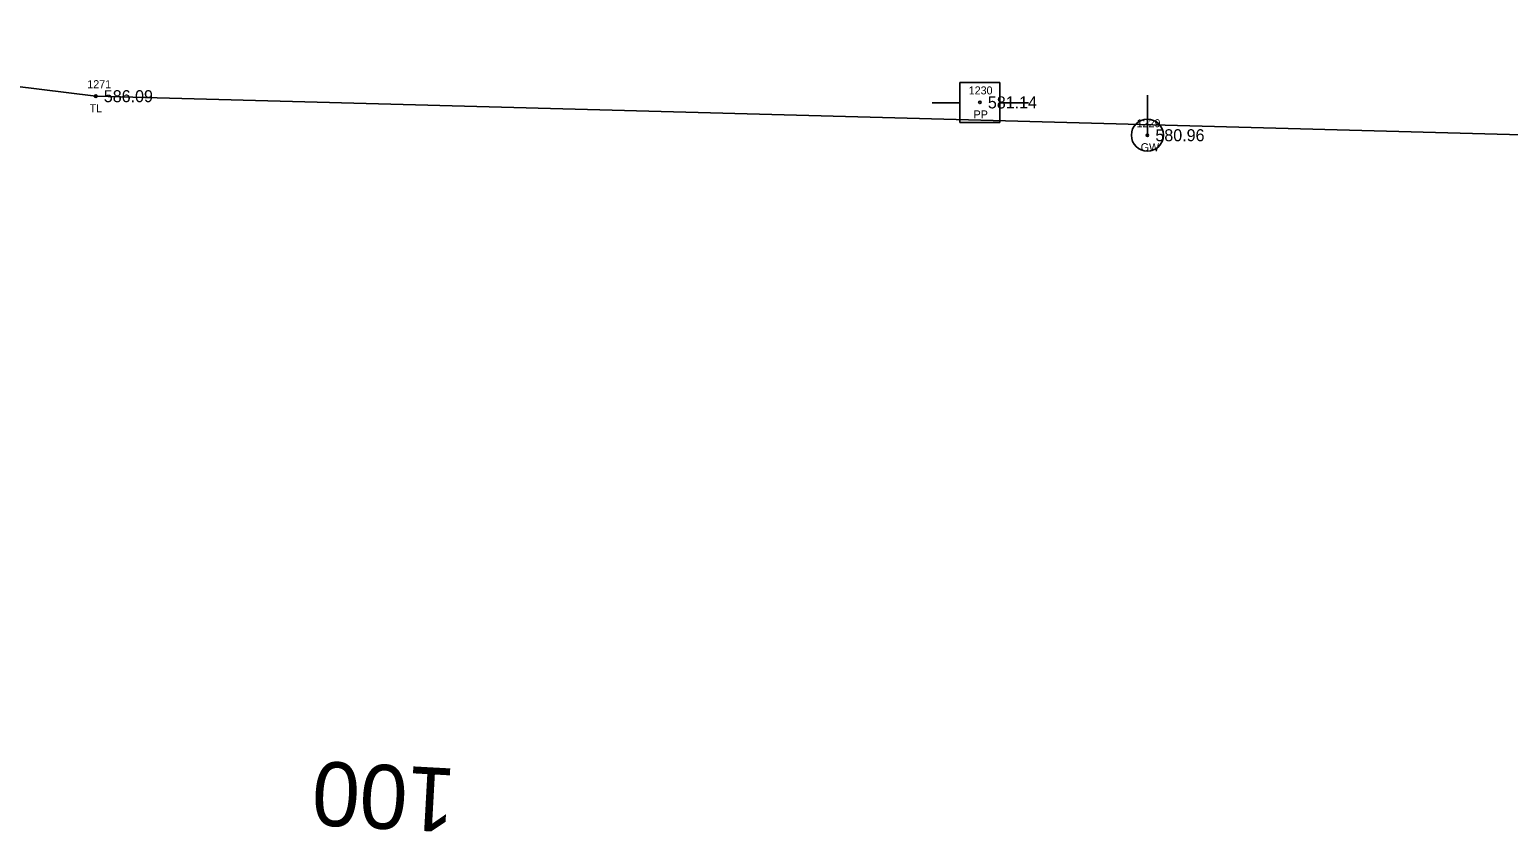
# Model space of a CAD drawing. Extents: x 1529475 to 1532053, y 876698 to 877911.
# Drawn here: x 1530599.7 to 1530784.5, y 877153.9 to 877254.2 of the extents above; entities that cross this region are included whole.
import ezdxf

# ---------------------------------------------------------------- set-up
doc = ezdxf.new("R2010")
doc.units = 0
for name, color, linetype in [('RD_EX_TX_UT_ELEV', 7, 'Continuous'), ('RD_EX_TX_VEG_ELEV', 7, 'Continuous'), ('RD_EX_UT', 7, 'Continuous'), ('RD_EX_UT_txCode', 7, 'Continuous'), ('RD_EX_VEG', 7, 'Continuous'), ('RD_EX_VEG_txCode', 7, 'Continuous'), ('RD_HC_Survey_ELEV', 7, 'Continuous'), ('RD_HC_TX_Sta50', 7, 'Continuous'), ('RD_SMD_Locator', 7, 'Continuous')]:
    doc.layers.add(name, color=color, linetype=linetype)

msp = doc.modelspace()

# ---------------------------------------------------------------- linework, layer by layer
at = {"layer": 'RD_EX_UT'}
for p, q in [((1530720.91, 877247.58), (1530715.91, 877247.58)), ((1530715.91, 877247.58), (1530715.91, 877242.58)), ((1530720.91, 877242.58), (1530720.91, 877247.58)), ((1530739.35, 877240.97), (1530739.35, 877245.97)), ((1530712.48, 877245.01), (1530715.95, 877245.01)), ((1530720.84, 877245.01), (1530724.48, 877245.01)), ((1530715.91, 877242.58), (1530720.91, 877242.58))]:
    msp.add_line(p, q, dxfattribs=at)
msp.add_circle((1530739.35, 877240.97), 2, dxfattribs=at)
at = {"layer": 'RD_EX_VEG'}
msp.add_lwpolyline([(1530806.62, 877154.57), (1530847.57, 877176.32), (1530815.29, 877240.21), (1530607.98, 877245.85), (1530502.71, 877258.91), (1530344.51, 877291.95), (1530315.54, 877291.5), (1530341.13, 877248.83)], dxfattribs=at)
at = {"layer": 'RD_SMD_Locator'}
for centre in [(1530607.98, 877245.85), (1530718.42, 877245.07), (1530739.35, 877240.97)]:
    msp.add_circle(centre, 0.15, dxfattribs=at)

# ---------------------------------------------------------------- texts
at = {"layer": 'RD_EX_TX_UT_ELEV'}
msp.add_text('580.96', height=1.5, dxfattribs=at).set_placement((1530740.35, 877240.22))
at = {"layer": 'RD_EX_TX_VEG_ELEV'}
msp.add_text('586.09', height=1.5, dxfattribs=at).set_placement((1530608.98, 877245.1))
at = {"layer": 'RD_EX_UT_txCode'}
for s, p in [('1230', (1530717.03, 877246.07)), ('PP', (1530717.64, 877243.07)), ('1229', (1530738.01, 877241.97)), ('GW', (1530738.51, 877238.97))]:
    msp.add_text(s, height=1, dxfattribs=at).set_placement(p)
at = {"layer": 'RD_EX_VEG_txCode'}
for s, p in [('1271', (1530606.92, 877246.85)), ('TL', (1530607.21, 877243.85))]:
    msp.add_text(s, height=1, dxfattribs=at).set_placement(p)
at = {"layer": 'RD_HC_Survey_ELEV'}
msp.add_text('581.14', height=1.5, dxfattribs=at).set_placement((1530719.42, 877244.32))
at = {"layer": 'RD_HC_TX_Sta50'}
msp.add_text('100', height=8, rotation=176.8557, dxfattribs=at).set_placement((1530653.07, 877161.77))

doc.saveas('drawing.dxf')
